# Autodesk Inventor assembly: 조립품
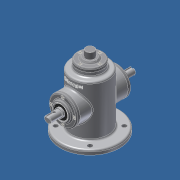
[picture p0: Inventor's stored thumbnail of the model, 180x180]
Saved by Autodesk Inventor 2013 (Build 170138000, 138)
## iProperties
Created: 2014-12
Part Number: 조립품
Document SubType Name: Assembly
Designer: CAD-B31
Author: CAD-B31
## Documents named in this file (12)
- C:\Users\CAD-B31\Desktop\441228V1005\답안조립품.iam
- C:\Users\CAD-B31\Desktop\441228V1005\본체.ipt
- C:\Users\CAD-B31\Desktop\441228V1005\편심축.ipt
- C:\Users\CAD-B31\Desktop\441228V1005\커버.ipt
- C:\Users\CAD-B31\Desktop\441228V1005\상단커버.ipt
- C:\Users\CAD-B31\Desktop\441228V1005\슬라이드.ipt
- C:\Users\CAD-B31\Desktop\441228V1005\베어링 6002.ipt
- 베어링 6002.ipt
- C:\Users\CAD-B31\Desktop\441228V1005\오일실.ipt
- 오일실.ipt
- C:\Users\CAD-B31\Desktop\441228V1005\M3x0.5x8.ipt
- M3x0.5.ipt
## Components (12 placed, 1 different names)
1. M3x0.5:2 — 각도:2
2. M3x0.5:4
3. M3x0.5:5
4. M3x0.5:6
5. M3x0.5:3 — 각도:1
6. M3x0.5:7
7. M3x0.5:8
8. M3x0.5:9
9. M3x0.5:1 — 각도:3
10. M3x0.5:10
11. M3x0.5:11
12. M3x0.5:12
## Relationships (3: Angle 3)
- 각도:1 [Angle]: M3x0.5:3
- 각도:2 [Angle]: M3x0.5:2
- 각도:3 [Angle]: M3x0.5:1
